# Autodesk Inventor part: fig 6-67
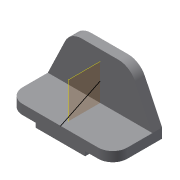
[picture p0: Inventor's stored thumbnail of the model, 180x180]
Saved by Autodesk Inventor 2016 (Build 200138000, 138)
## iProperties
Shininess: 77.0
Length Units: 11269
Angle Units: 11279
Time Units: 11290
Mass Units: 11283
Length Display Precision: 3
Angle Display Precision: 2
Created: 2001-12
Part Number: fig 6-67
Document SubType Name: Modeling
Designer: Renu Muthoo
Density: 1 g/cm^3
Material: Generic
Appearance: Default
Density: 0.0
Volumn: 0.0
Area: 0.0
PropertySet Name: Model Information
Control State: 0
Master: False
Checked Out: False
Author: Renu Muthoo
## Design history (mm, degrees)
node "Sketch1"
sketch "Sketch2"
  geometry: L1 (-67.219, 19.116)-(148.781, 19.116); L2 (148.781, 19.116)-(148.781, -0.884); L3 (-67.219, -0.884)-(-67.219, 19.116); L4 (-10.219, -0.884)-(-10.219, -9.884); L5 (-10.219, -9.884)-(91.781, -9.884); L6 (91.781, -9.884)-(91.781, -0.884); L7 (148.781, -0.884)-(91.781, -0.884); L8 (-10.219, -0.884)-(-67.219, -0.884)
  constraints: 16 end point, 5 parallel, 4 perpendicular, 2 equal length, 1 horizontal
  dimensions: "d0" = 102 distance of L4.end L5.end; "d1" = 57 distance of L4.start L3.start; "d2" = 29 distance between parallel lines of L1 L5; "d3" = 20 distance of L1.end L2.end
extrude "Extrusion1" new body sketch "Sketch2" distance "d4" = 102; taper "d5" = 0 deg
sketch "Sketch3"
  geometry: L1 (67.219, -19.116)-(-148.781, -19.116) reference; L2 (67.219, -19.116)-(31.475, -93.564); L3 (-2.781, -115.116)-(-78.781, -115.116); L4 (-113.038, -93.564)-(-148.781, -19.116); A1 r 38 centre (-2.781, -77.116) between (-2.781, -115.116) and (31.475, -93.564); A2 r 38 centre (-78.781, -77.116) between (-113.038, -93.564) and (-78.781, -115.116)
  constraints: 6 end point, 4 point on circle, 4 tangent, 2 centre point, 1 equal length, 1 equal radius, 1 parallel
  dimensions: "d6" = 96 distance between parallel lines of L3 L1; "d7" = 38 radius of A1; "d8" = 76 distance of A2.centre A1.centre
extrude "Extrusion2" join sketch "Sketch3" distance "d9" = 20; taper "d10" = 0 deg
fillet "Fillet1" dims "d11" = 30
workplane "Work Plane1"
sketch "Sketch7"
  geometry: L1 (0, -82)-(-39.557, 0)
  constraints: 2 end point
body "Solid1"
other parameters: "d12" = -108
